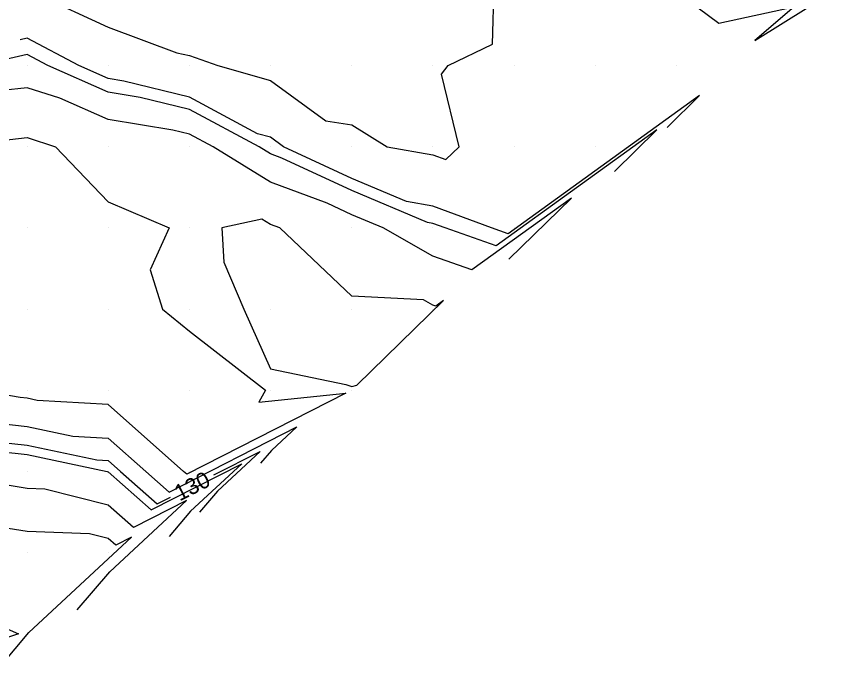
# Model space of a CAD drawing. Extents: x 2354170 to 2357230, y 866100 to 868290.
# Drawn here: x 2355708.7 to 2355811.3, y 866493.9 to 866576 of the extents above; entities that cross this region are included whole.
import ezdxf

# ---------------------------------------------------------------- set-up
doc = ezdxf.new("R2010")
doc.units = 0
for name, color, linetype in [('Default', 7, 'Continuous'), ('DTM Contours Major', 7, 'Continuous'), ('DTM Contours Major Text', 7, 'Continuous'), ('Exist DTM QL2 LIDAR Elevation Point', 7, 'Continuous')]:
    doc.layers.add(name, color=color, linetype=linetype)

msp = doc.modelspace()

# ---------------------------------------------------------------- linework, layer by layer
at = {"layer": 'Default'}
for points in [[(2355811.31, 866581.33), (2355809.98, 866582.63), (2355804.07, 866585.92), (2355799.98, 866587.77), (2355792.69, 866587.3), (2355789.98, 866582.14), (2355789.64, 866580.01), (2355789.98, 866579.17), (2355795.21, 866575.24), (2355804.49, 866577.26), (2355799.64, 866573.11), (2355806.31, 866577.25), (2355808.64, 866578.94), (2355808.33, 866578.63)], [(2355711.19, 866578.79), (2355719.98, 866574.76), (2355728.42, 866571.57), (2355729.98, 866571.27), (2355733.49, 866570.01), (2355739.98, 866568.19), (2355746.78, 866563.21), (2355749.98, 866562.7), (2355754.34, 866560.01), (2355759.98, 866559.01), (2355761.56, 866558.42), (2355763.23, 866560.01), (2355761.06, 866568.93), (2355761.87, 866570.01), (2355767.34, 866572.64), (2355767.53, 866580.01)], [(2355788.84, 866562.39), (2355792.86, 866566.31), (2355769.25, 866549.28), (2355767.19, 866550.01), (2355759.98, 866552.68), (2355756.73, 866553.25), (2355749.98, 866556.09), (2355741.57, 866560.01), (2355739.98, 866561.17), (2355738.37, 866561.62), (2355729.98, 866566.1), (2355721.9, 866568.09), (2355719.98, 866568.4), (2355716.34, 866570.01), (2355709.98, 866573.38), (2355709.1, 866573.18)], [(2355769.36, 866546.15), (2355777.08, 866553.69), (2355764.8, 866544.83), (2355759.98, 866546.53), (2355753.84, 866550.01), (2355749.98, 866551.62), (2355746.95, 866553.04), (2355739.98, 866555.65), (2355732.89, 866560.01), (2355729.98, 866561.56), (2355727.92, 866562.07), (2355719.98, 866563.35), (2355713.99, 866566), (2355709.98, 866567.28), (2355706.91, 866566.93)], [(2355699.98, 866560.01), (2355709.98, 866561.13), (2355713.49, 866560.01), (2355719.98, 866553.23), (2355727.47, 866550.01), (2355725.13, 866544.86), (2355726.64, 866540.01), (2355729.98, 866537.28), (2355739.37, 866530.01), (2355738.53, 866528.55), (2355749.27, 866529.65), (2355729.64, 866519.67)], [(2355761.3, 866541.06), (2355760.35, 866540.38), (2355759.98, 866540.51), (2355758.82, 866541.17), (2355749.98, 866541.6), (2355741.1, 866550.01), (2355739.98, 866550.42), (2355738.89, 866551.09), (2355733.99, 866550.01), (2355734.2, 866545.79), (2355736.7, 866540.01), (2355739.98, 866532.64), (2355749.26, 866530.73), (2355749.98, 866530.46), (2355750.62, 866530.65), (2355761.3, 866541.06)], [(2355729.64, 866519.67), (2355729.26, 866520), (2355719.98, 866528.26), (2355711.21, 866528.77), (2355709.98, 866529.03), (2355709.1, 866529.13), (2355703.87, 866530.01)], [(2355705.97, 866526), (2355709.98, 866525.57), (2355715.62, 866524.37), (2355719.98, 866524.11), (2355724.59, 866520), (2355727.46, 866517.48), (2355743.22, 866525.5), (2355740.08, 866522.58), (2355738.75, 866521.02)], [(2355691.53, 866524.06), (2355693.06, 866523.09), (2355699.98, 866523.35), (2355702.84, 866522.87), (2355709.98, 866522.1), (2355719.82, 866520), (2355719.98, 866519.96), (2355725.27, 866515.3), (2355736.43, 866520.97), (2355730.12, 866515.11), (2355727.46, 866511.99)], [(2355716.16, 866502.95), (2355720.16, 866507.64), (2355729.63, 866516.44), (2355723.08, 866513.11), (2355719.98, 866515.85), (2355712.15, 866517.83), (2355709.98, 866517.91), (2355700.53, 866519.46)], [(2355704.87, 866493.91), (2355710.2, 866500.17), (2355722.84, 866511.91), (2355720.9, 866510.92), (2355719.98, 866511.74), (2355717.66, 866512.32), (2355709.98, 866512.6), (2355706.87, 866513.11)], [(2355702.71, 866502.74), (2355708.91, 866500), (2355699.98, 866497.02)]]:
    msp.add_lwpolyline(points, dxfattribs=at)
at = {"layer": 'DTM Contours Major'}
for points in [[(2355782.35, 866556.98), (2355787.6, 866562.1), (2355767.77, 866547.8), (2355761.5, 866550.01), (2355759.98, 866550.57), (2355759.3, 866550.69), (2355749.98, 866554.6), (2355741.38, 866558.61), (2355739.98, 866559.13), (2355738.56, 866560.01), (2355729.98, 866564.59), (2355723.9, 866566.08), (2355719.98, 866566.72), (2355712.53, 866570.01), (2355709.98, 866571.36), (2355704.61, 866570.16)], [(2355698.99, 866568.41), (2355695.9, 866565.92), (2355690.24, 866560.85), (2355689.25, 866559.91), (2355681.21, 866551.24), (2355680.16, 866550.01), (2355679.98, 866549.75), (2355674.75, 866540.01), (2355679.98, 866530.76), (2355681.63, 866530.01), (2355689.98, 866527.12), (2355694.33, 866524.35), (2355699.98, 866524.56), (2355703.88, 866523.91), (2355709.98, 866523.26), (2355718.56, 866521.43), (2355719.98, 866521.35), (2355721.49, 866520), (2355726, 866516.02), (2355727.65, 866516.86)], [(2355732.99, 866519.58), (2355738.69, 866522.48), (2355733.44, 866517.6), (2355731.22, 866515)]]:
    msp.add_lwpolyline(points, dxfattribs=at)
at = {"layer": 'Exist DTM QL2 LIDAR Elevation Point'}
for p, q in [((2355709.98, 866570.01), (2355709.98, 866570.01)), ((2355719.98, 866570.01), (2355719.98, 866570.01)), ((2355729.98, 866570.01), (2355729.98, 866570.01)), ((2355739.98, 866570.01), (2355739.98, 866570.01)), ((2355749.98, 866570.01), (2355749.98, 866570.01)), ((2355759.98, 866570.01), (2355759.98, 866570.01)), ((2355769.98, 866570.01), (2355769.98, 866570.01)), ((2355779.98, 866570.01), (2355779.98, 866570.01)), ((2355789.98, 866570.01), (2355789.98, 866570.01)), ((2355709.98, 866560.01), (2355709.98, 866560.01)), ((2355719.98, 866560.01), (2355719.98, 866560.01)), ((2355729.98, 866560.01), (2355729.98, 866560.01)), ((2355739.98, 866560.01), (2355739.98, 866560.01)), ((2355749.98, 866560.01), (2355749.98, 866560.01)), ((2355759.98, 866560.01), (2355759.98, 866560.01)), ((2355769.98, 866560.01), (2355769.98, 866560.01)), ((2355779.98, 866560.01), (2355779.98, 866560.01)), ((2355709.98, 866550.01), (2355709.98, 866550.01)), ((2355719.98, 866550.01), (2355719.98, 866550.01)), ((2355729.98, 866550.01), (2355729.98, 866550.01)), ((2355739.98, 866550.01), (2355739.98, 866550.01)), ((2355749.98, 866550.01), (2355749.98, 866550.01)), ((2355759.98, 866550.01), (2355759.98, 866550.01)), ((2355769.98, 866550.01), (2355769.98, 866550.01)), ((2355709.98, 866540.01), (2355709.98, 866540.01)), ((2355719.98, 866540.01), (2355719.98, 866540.01)), ((2355729.98, 866540.01), (2355729.98, 866540.01)), ((2355739.98, 866540.01), (2355739.98, 866540.01)), ((2355749.98, 866540.01), (2355749.98, 866540.01)), ((2355759.98, 866540.01), (2355759.98, 866540.01)), ((2355709.98, 866530.01), (2355709.98, 866530.01)), ((2355719.98, 866530.01), (2355719.98, 866530.01)), ((2355729.98, 866530.01), (2355729.98, 866530.01)), ((2355739.98, 866530.01), (2355739.98, 866530.01)), ((2355749.98, 866530.01), (2355749.98, 866530.01)), ((2355709.98, 866520), (2355709.98, 866520)), ((2355719.98, 866520), (2355719.98, 866520)), ((2355729.98, 866520), (2355729.98, 866520)), ((2355709.98, 866510), (2355709.98, 866510)), ((2355719.98, 866510), (2355719.98, 866510)), ((2355709.98, 866500), (2355709.98, 866500))]:
    msp.add_line(p, q, dxfattribs=at)

# ---------------------------------------------------------------- texts
at = {"layer": 'DTM Contours Major Text'}
msp.add_text('130', height=2, rotation=26.9593, dxfattribs=at).set_placement((2355728.77, 866516.31))

doc.saveas('drawing.dxf')
